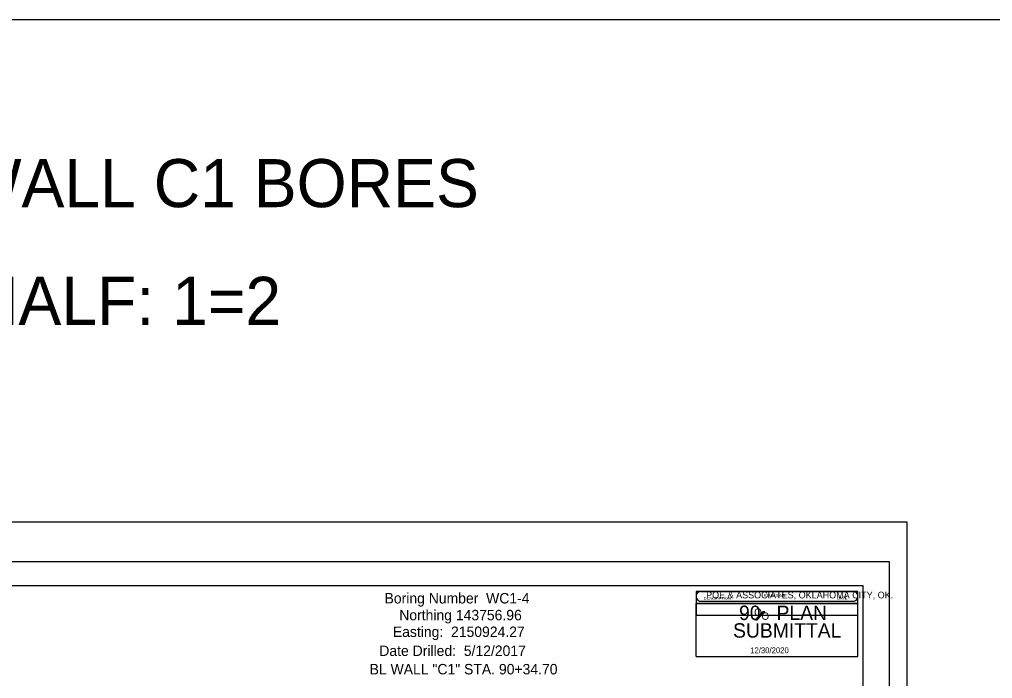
# Model space of a CAD drawing. Extents: x -6 to 173, y 24 to 64.
# Drawn here: x 65.85 to 86.09, y 50.71 to 64.42 of the extents above; entities that cross this region are included whole.
import ezdxf

# ---------------------------------------------------------------- set-up
doc = ezdxf.new("R2010")
doc.units = 0
for name, color, linetype in [('S', 7, 'Continuous'), ('SHT_Plot_Shape_Full', 7, 'Continuous'), ('SHT_Plot_Shape_Half', 7, 'Continuous'), ('SHT_Sheet_Border', 7, 'Continuous'), ('SHT_Stamp_90_Submit', 7, 'Continuous'), ('SHT_Stamp_Rev_Block', 7, 'Continuous')]:
    doc.layers.add(name, color=color, linetype=linetype)

msp = doc.modelspace()

# ---------------------------------------------------------------- linework, layer by layer
at = {"layer": 'S'}
msp.add_lwpolyline([(-6.024, 64.421), (172.576, 64.421), (172.576, 25.783), (-6.024, 25.783)], close=True, dxfattribs=at)
at = {"layer": 'SHT_Plot_Shape_Full'}
msp.add_lwpolyline([(48.302, 53.971), (84.302, 53.971), (84.302, 29.971), (48.302, 29.971)], close=True, dxfattribs=at)
at = {"layer": 'SHT_Plot_Shape_Half'}
msp.add_lwpolyline([(49.939, 53.146), (83.939, 53.146), (83.939, 31.146), (49.939, 31.146)], close=True, dxfattribs=at)
at = {"layer": 'SHT_Sheet_Border'}
msp.add_lwpolyline([(51.889, 52.646), (83.389, 52.646), (83.389, 31.646), (51.889, 31.646)], close=True, dxfattribs=at)
at = {"layer": 'SHT_Stamp_90_Submit'}
for p, q in [((80.02, 52.522), (83.186, 52.522)), ((79.92, 52.272), (83.286, 52.272)), ((79.92, 51.173), (79.92, 52.272)), ((80.02, 52.322), (83.186, 52.322)), ((83.286, 51.173), (83.286, 52.272)), ((81.163, 51.934), (81.319, 52.107)), ((81.181, 51.934), (81.337, 52.107)), ((81.186, 51.934), (81.341, 52.107)), ((81.194, 51.934), (81.349, 52.107)), ((81.319, 52.107), (81.349, 52.107)), ((81.163, 51.934), (81.194, 51.934)), ((79.92, 51.173), (83.286, 51.173))]:
    msp.add_line(p, q, dxfattribs=at)
for centre, start, end in [((80.02, 52.422), 89.9952, 270), ((83.186, 52.422), 270, 90.0048)]:
    msp.add_arc(centre, 0.1, start, end, dxfattribs=at)
at = {"layer": 'SHT_Stamp_Rev_Block'}
for p, q in [((79.92, 52.522), (79.92, 52.022)), ((83.286, 52.522), (79.92, 52.522)), ((83.286, 52.022), (83.286, 52.522)), ((83.286, 52.272), (79.92, 52.272)), ((83.286, 52.022), (79.92, 52.022))]:
    msp.add_line(p, q, dxfattribs=at)

# ---------------------------------------------------------------- texts
for s, p in [('Boring Number  WC1-4', (73.441, 52.275)), ('Northing 143756.96', (73.747, 51.925)), ('Easting:  2150924.27', (73.614, 51.578)), ('Date Drilled:  5/12/2017', (73.332, 51.183)), ('BL WALL "C1" STA. 90+34.70', (73.131, 50.8))]:
    msp.add_text(s, height=0.217).set_placement(p)
at = {"layer": 'S'}
for s, p in [('PHASE 2 WALL C1 BORES', (58.607, 60.517)), ('FULL: 1=1   HALF: 1=2', (57.464, 58.069))]:
    msp.add_text(s, height=1, dxfattribs=at).set_placement(p)
at = {"layer": 'SHT_Stamp_90_Submit'}
for s, height, p in [('POE & ASSOCIATES, OKLAHOMA CITY, OK.', 0.14, (80.13, 52.38)), ('90   PLAN', 0.3, (80.815, 51.93)), ('O', 0.153, (81.129, 52.019)), ('O', 0.153, (81.281, 51.935)), ('SUBMITTAL', 0.3, (80.691, 51.564)), ('12/30/2020', 0.12, (81.046, 51.241))]:
    msp.add_text(s, height=height, dxfattribs=at).set_placement(p)
at = {"layer": 'SHT_Stamp_Rev_Block'}
for s, height, p in [('REVISIONS', 0.06, (81.328, 52.41)), ('DESCRIPTION', 0.05999, (80.08, 52.351)), ('DATE', 0.06, (82.849, 52.355))]:
    msp.add_text(s, height=height, dxfattribs=at).set_placement(p)

doc.saveas('drawing.dxf')
